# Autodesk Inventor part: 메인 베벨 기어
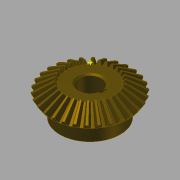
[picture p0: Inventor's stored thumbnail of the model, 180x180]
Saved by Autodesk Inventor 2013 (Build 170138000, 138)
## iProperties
Created: 2014-10
Part Number: 메인 베벨 기어
Material: 강철, 탄소
Document SubType Name: Modeling
Designer: KYOUNG IL JANG
Categories: <?xml version="1.0" encoding="UTF-16"?> <MemberInstance><Categories><FamilyTemplate><FamilyTemplateParameter ValueType="xs:double" Id="1" ObjectReferenceKey="da
Mass: 269.583 g
Surface Area: 108.837 cm^2
Volume: 34.2981 cm^3
Density: 7.86 g/cm^3
CustomPartVersion: 1
Author: SeoGD™ [www.esajin.kr]
Revision Number: 1
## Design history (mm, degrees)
node "맨 위 점"
node "메쉬 평면2"
sketch "톱니 본체 스케치"
  geometry: L1 (0, 0)-(28.669, -21.997); L2 (28.669, -21.997)-(31.109, -18.336); L3 (31.109, -18.336)-(0, 0); L4 (30, -20)-(0, 0); L5 (17.219, -13.212)-(18.685, -11.013); L6 (28.669, -21.997)-(17.219, -13.212); L7 (31.109, -18.336)-(18.685, -11.013); L8 (0, -39.387)-(0, 6.564) reference; L9 (0, -20)-(31.109, -20)
  constraints: 16 end point, 4 point on line, 3 perpendicular, 2 collinear, 1 horizontal alignment, 1 vertical alignment
  dimensions: "d0" = 60 diameter of L4.start L8 (= da_de); "d1" = 57.33744 diameter of L1.end L8 (= da_dfe); "d2" = 62.2188 diameter of L2.end L8 (= da_dae); "d3" = 14.4 distance between parallel lines of L2 L5 (= da_b); "d4" = 18.3359 vertical distance of L2.end L1.start (= da_ve)
revolve "톱니 본체" sketch "톱니 본체 스케치" stored, may be unused: angle "d5" = 90 deg
node "시작점"
node "톱니 평면"
sketch "시작 스케치"
  geometry: L1 (0, -23.505)-(0, 10.645) reference; L2 (-0.709, -2.928)-(0.709, -2.928); A1 r 19.188 centre (-19.457, -7.014) between (-0.709, -2.928) and (-3.232, 3.229); A2 r 19.188 centre (19.457, -7.014) between (3.232, 3.229) and (0.709, -2.928); A3 r 57.403 centre (0, -54.083) between (3.232, 3.229) and (-3.232, 3.229); 1 further point
  constraints: 6 point on circle, 3 centre point, 3 symmetric about line, 2 end point, 1 coincident, 1 perpendicular, 1 other
  dimensions: "d7" = 19.18795 radius of A1 (= fd_rr); "d8" = 19.45712 horizontal distance of point (0, -54.083) A1.centre (= fd_x); "d9" = 47.06905 vertical distance of point (0, -54.083) A1.centre (= fd_y); "d57" = 57.40327 radius of A3 (= 0.5 x fd_dva + 0.3 x da_he); "d58" = 51.15527 distance from line of A3.centre L2 (= 0.5 x fd_dva - 1.12 x da_he)
node "끝점"
  node "끝 평면"
sketch "3D 스케치 오른쪽"
  node "Helical Curve Right" dims "d65" = 229.90621 (computed from da_dm, da_delta, da_beta), "d66" = 31.5, "d67" = 60 (= da_de), "d68" = -9.82794 (= -da_delta), "d69" = 8.10972 (computed from fd_loft, da_delta)
node "끝 평면 오른쪽"
sketch "끝 스케치 오른쪽"
  geometry: L1 (0, -41.54)-(0, 13.178) reference; L2 (-0.422, -1.69)-(0.422, -1.69); A1 r 11.427 centre (-11.587, -4.123) between (-0.422, -1.69) and (-1.925, 1.977); A2 r 11.427 centre (11.587, -4.123) between (1.925, 1.977) and (0.422, -1.69); A3 r 34.184 centre (0, -32.153) between (1.925, 1.977) and (-1.925, 1.977); 1 further point
  constraints: 6 point on circle, 3 centre point, 3 symmetric about line, 2 end point, 1 coincident, 1 perpendicular, 1 other
  dimensions: "d70" = 11.58699 horizontal distance of A3.centre A1.centre (computed from fd_x, fd_ratio); "d71" = 28.03028 vertical distance of point (0, -32.153) A1.centre (computed from fd_y, fd_ratio); "d72" = 11.4267 radius of A1 (computed from fd_rr, fd_ratio); "d73" = 30.46369 distance from line of point (0, -32.153) L2 (computed from d58, fd_ratio); "d74" = 34.18446 radius of A3 (computed from d57, fd_ratio)
feature "로프트 오른쪽" sketch "끝 스케치 오른쪽" dims "d75" = 0, "d77" = 0, "d79" = 0, "d80" = 90 deg, "d85" = 20, "d92" = 90 deg, "d93" = 90 deg, "da_teethtype" = 0 [user parameter]
sketch "3D 스케치 왼쪽"
  node "Helical Curve Left" dims "d26" = 229.90621 (computed from da_dm, da_delta, da_beta), "d27" = 8.10972 (computed from fd_loft, da_delta), "d28" = 60 (= da_de), "d29" = -9.82794 (= -da_delta)
node "끝 평면 왼쪽"
sketch "끝 스케치 왼쪽" dims "d56" = 10.3728 (derived)
  geometry: L1 (0, -43.753)-(0, 15.405) reference; L2 (-0.422, -1.678)-(0.422, -1.678); A1 r 11.427 centre (-11.587, -4.111) between (-0.422, -1.678) and (-1.925, 1.988); A2 r 11.427 centre (11.587, -4.111) between (1.925, 1.988) and (0.422, -1.678); A3 r 34.184 centre (0, -32.142) between (1.925, 1.988) and (-1.925, 1.988); 2 further points; 1 other entity
  constraints: 6 point on circle, 3 centre point, 3 symmetric about line, 2 end point, 1 coincident, 2 other
  dimensions: "d30" = 11.4267 radius of A1 (computed from fd_rr, fd_ratio); "d31" = 11.58699 horizontal distance of point (0, -32.142) A1.centre (computed from fd_x, fd_ratio); "d32" = 28.03028 vertical distance of A1.centre point (0, -32.142) (computed from fd_y, fd_ratio); "d61" = 34.18446 radius of A3 (computed from d57, fd_ratio); "d62" = 30.46369 distance from line of point (0, -32.142) L2 (computed from d58, fd_ratio)
feature "로프트 왼쪽" sketch "끝 스케치 왼쪽" dims "d35" = 0, "d37" = 0, "d39" = 0, "d40" = 90 deg, "d84" = 10, "d90" = 90 deg, "d91" = 90 deg, "da_teethtype" = 0 [user parameter]
sketch "본체 스케치"
  geometry: L1 (0, -35.038)-(0, -19.531) reference; L2 (28.669, -21.997)-(17.219, -13.212) reference; L3 (17.219, -13.212)-(0, -13.212); L4 (28.669, -21.997)-(0, -21.997)
  constraints: 4 end point, 2 perpendicular, 2 point on line
revolve "본체 고정" sketch "본체 스케치" stored, may be unused: angle "d46" = 90 deg
feature "피치 지름" dims angle "d47" = 90 deg
sketch "스케치8"
  geometry: C1 r 22.5 at (0, 0); 1 further point
  constraints: 1 centre point, 1 coincident
  dimensions: "d94" = 45 diameter of C1
extrude "돌출1" join sketch "스케치8" distance "d95" = 13; taper "d96" = 0 deg
sketch "스케치9"
  geometry: 1 further point
hole "구멍1" sketch "스케치9" at (0, 0) diameter "d97" = 17; stored, may be unused: countersink angle "d101" = 90 deg, drill point angle "d103" = 118 deg; dims "d98" = 6, "d99" = 4, "d100" = 2, "d102" = 8
sketch "스케치10"
  geometry: L1 (8.124, 2.5)-(10.8, 2.5); L2 (10.8, 2.5)-(10.8, -2.5); L3 (10.8, -2.5)-(8.124, -2.5); A1 r 8.5 centre (0, 0) between (8.124, 2.5) and (8.124, -2.5) reference; 1 further point
  constraints: 6 end point, 2 parallel, 2 point on circle, 1 horizontal, 1 perpendicular
  dimensions: "d104" = 5 distance of L1.end L2.end; "d112" = 19.3 dimension on A1 L2
extrude "돌출2" cut sketch "스케치10" stored distance "d106" = 10; taper "d107" = 0 deg
chamfer "모따기1" distance "d108" = 1; stored, may be unused: second distance "d109" = 2, angle "d110" = 45 deg
fillet "모깎기1" dims "d111" = 2
body "Solid1"
feature "로프트" dims "d17" = 0, "d18" = 90 deg, "d19" = 0, "d20" = 90 deg, "d89" = 0, "da_teethtype" = 0 [user parameter]
pattern_circular "원형 패턴" dims angle "d22" = 360 deg, "d88" = 0, "da_teethtype" = 0 [user parameter]
pattern_circular "원형 패턴 오른쪽" dims angle "d82" = 360 deg, "da_teethtype" = 0 [user parameter]
pattern_circular "원형 패턴 왼쪽" dims angle "d42" = 360 deg, "da_teethtype" = 0 [user parameter]
sketch "끝 스케치"
  geometry: L1 (0, -15.359)-(0, 6.983) reference; L2 (-0.422, -1.69)-(0.422, -1.69); A1 r 11.427 centre (-11.587, -4.123) between (-0.422, -1.69) and (-1.925, 1.977); A2 r 11.427 centre (11.587, -4.123) between (1.925, 1.977) and (0.422, -1.69); A3 r 34.184 centre (0, -32.153) between (1.925, 1.977) and (-1.925, 1.977); 1 further point
  constraints: 6 point on circle, 3 centre point, 3 symmetric about line, 2 end point, 1 coincident, 1 other
  dimensions: "d12" = 11.4267 radius of A1 (computed from fd_rr, fd_ratio); "d15" = 11.58699 horizontal distance of A1.centre point (0, -32.153) (computed from fd_x, fd_ratio); "d16" = 28.03028 vertical distance of A1.centre point (0, -32.153) (computed from fd_y, fd_ratio); "d59" = 34.18446 radius of A3 (computed from d57, fd_ratio); "d60" = 30.46369 distance from line of A3.centre L2 (computed from d58, fd_ratio)
sketch "Sketch6"
  geometry: L1 (30, -20)-(0, 0) reference; L2 (0, -37.8)-(0, 6.3) reference
body "Srf1"
other parameters: "da_b" = 14.4 [user parameter; used in 2 equation terms], "da_de" = 60 [user parameter; used in 4 equation terms], "da_dae" = 62.2188 [user parameter; used in 2 equation terms], "da_dfe" = 57.33744 [user parameter; used in 1 equation term], "da_le" = 36.05551 [user parameter; used in 1 equation term], "da_omega" = 90 deg [user parameter; used in 1 equation term], "da_beta" = 0 [user parameter; used in 2 equation terms], "da_delta" = 9.82794 [user parameter; used in 8 equation terms], "da_alpha" = 20 deg [user parameter; used in 2 equation terms], "da_he" = 4.4 [user parameter; used in 4 equation terms], "da_ve" = 18.3359 [user parameter; used in 1 equation term], "fd_dv" = 108.16654 (computed from da_de, da_delta) [user parameter; used in 1 equation term], "fd_dva" = 112.16654 (computed from da_dae, da_delta) [user parameter; used in 3 equation terms], "fd_dvb" = 101.6433 (computed from fd_dv, da_alpha) [user parameter; used in 2 equation terms], "da_zv" = 540.83269 [user parameter; used in 1 equation term], "fd_loft" = 14.62 (= da_b + 0.05 x da_he) [user parameter; used in 4 equation terms], "fd_ratio" = 5.95514 (computed from da_le, fd_loft) [user parameter; used in 15 equation terms], "fd_rr" = 19.18795 (computed from fd_dd, fd_dvb) [user parameter; used in 6 equation terms], "fd_angle" = 0.29367 (computed from da_zv) [user parameter; used in 4 equation terms], "fd_x1" = 1.58802 (computed from da_dvw, fd_angle) [user parameter; used in 1 equation term], "fd_y1" = 54.05995 (computed from da_dvw, fd_angle) [user parameter; used in 1 equation term], "fd_x2" = 17.8691 (computed from fd_rr, fd_angle2, fd_angle) [user parameter; used in 1 equation term], "fd_y2" = 6.9909 (computed from fd_rr, fd_angle2, fd_angle) [user parameter; used in 1 equation term], "fd_x" = 19.45712 (= fd_x1 + fd_x2) [user parameter; used in 4 equation terms], "fd_y" = 47.06905 (= fd_y1 - fd_y2) [user parameter; used in 4 equation terms], "fd_angle2" = 3.43555 (computed from fd_dvb, fd_dd, da_alpha) [user parameter; used in 2 equation terms], "fd_dd" = 108.64654 (= fd_dva - 0.8 x da_he) [user parameter; used in 2 equation terms], "da_dvw" = 108.16654 [user parameter; used in 2 equation terms], "d11" = 14.62 (= fd_loft), "da_dm" = 48.01848 [user parameter; used in 2 equation terms], "da_x" = 0 [user parameter], "da_m" = 2 [user parameter], "d48" = 0, "d49" = 0, "d50" = 90 deg (= da_omega), "d51" = 6 deg (computed from da_z), "d52" = 0, "d53" = 0, "d54" = 0
